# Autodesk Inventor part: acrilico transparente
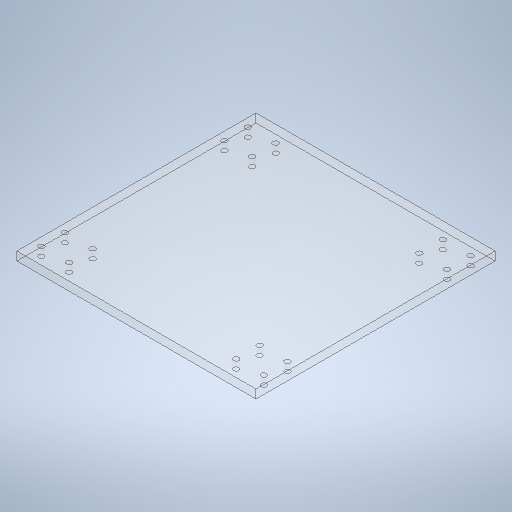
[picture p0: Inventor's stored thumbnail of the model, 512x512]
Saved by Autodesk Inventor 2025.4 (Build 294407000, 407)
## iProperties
Created: 2026-04
Part Number: acrilico transparente
Material: PET Plastic
Document SubType Name: Modeling
Designer: I11112
Density: 1.541 g/cm^3
Appearance: Polycarbonate - Clear
Author: I11112
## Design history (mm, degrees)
sketch "Sketch1"
  geometry: L1 (0, 0)-(220, 0); L2 (220, 0)-(220, -220); L3 (220, -220)-(0, -220); L4 (0, -220)-(0, 0)
  constraints: 8 end point, 2 parallel, 1 horizontal, 1 perpendicular
  dimensions: "d0" = 220 distance of L2.end L3.end; "d1" = 220 distance of L1.end L2.end
extrude "Extrusion1" new body sketch "Sketch1" distance "d2" = 8; taper "d3" = 0 deg
sketch "Sketch2"
  geometry: L1 (-220, 220)-(-220, 0) reference; L2 (0, 220)-(-220, 220) reference; L3 (0, 0)-(0, 220) reference; L4 (-212.5, 205)-(-186.9, 205); L5 (-212.5, 205)-(-199.7, 205); L6 (-200.3, 225.221)-(-200.3, 193.976); L7 (-33.1, 205)-(-7.5, 205); L8 (-7.5, 205)-(-20.3, 205); L9 (-20.3, 205)-(-20.3, 225.334); L10 (-212.5, 36.6)-(-199.7, 36.6); L11 (-200.3, 56.64)-(-200.3, 25.394); L12 (-212.5, 36.6)-(-186.9, 36.6); L13 (-20.3, 36.419)-(-20.3, 56.753); L14 (-33.1, 36.419)-(-7.5, 36.419); L15 (-7.5, 36.419)-(-20.3, 36.419); L16 (-220, 0)-(0, 0) reference; C1 r 2.5 at (-212.5, 205); C2 r 2.5 at (-186.9, 205); C3 r 2.5 at (-212.5, 183.4); C4 r 2.5 at (-186.9, 183.4); C5 r 2.5 at (-33.1, 205); C6 r 2.5 at (-7.5, 205); C7 r 2.5 at (-33.1, 183.4); C8 r 2.5 at (-7.5, 183.4); C9 r 2.5 at (-186.9, 36.6); C10 r 2.5 at (-212.5, 36.6); C11 r 2.5 at (-186.9, 15); C12 r 2.5 at (-212.5, 15); C13 r 2.5 at (-33.1, 36.419); C14 r 2.5 at (-33.1, 14.819); C15 r 2.5 at (-7.5, 14.819); C16 r 2.5 at (-7.5, 36.419); 4 further points
  constraints: 24 end point, 16 centre point, 8 midpoint, 8 vertical alignment, 4 horizontal, 4 vertical
  dimensions: "d4" = 5 diameter of C1; "d5" = 5 diameter of C2; "d6" = 5 diameter of C3; "d7" = 5 diameter of C4; "d8" = 25.6 distance of L4.end L4.start; "d9" = 21.6 distance of C3.centre L4.start; "d10" = 7.5 distance from line of L1 C3.centre; "d11" = 15 distance from line of L2 L4.start; "d12" = 21.6 distance of C4.centre L4.end (= d9); "d13" = 5 diameter of C5; "d14" = 5 diameter of C6; "d15" = 5 diameter of C7; "d16" = 5 diameter of C8; "d17" = 25.6 distance of L7.end L7.start; "d18" = 21.6 distance of C7.centre L7.start; "d19" = 21.6 distance of C8.centre L7.end (= d18); "d20" = 7.5 distance from line of L3 C8.centre; "d21" = 15 distance from line of L2 L7.end; "d22" = 180 distance from line of point (-20.3, 215.167) L6; "d23" = 13.4 horizontal distance of L4.end point (-200.3, 209.598) (derived); "d24" = 5 diameter of C10; "d25" = 5 diameter of C9; "d26" = 5 diameter of C12; "d27" = 5 diameter of C11; "d28" = 25.6 distance of L12.end L10.start; "d29" = 21.6 distance of C12.centre L10.start; "d30" = 21.6 distance of C11.centre L12.end (= d29); "d31" = 5 diameter of C13; "d32" = 5 diameter of C16; "d33" = 5 diameter of C14; "d34" = 5 diameter of C15; "d35" = 25.6 distance of L14.end L14.start; "d36" = 21.6 distance of C14.centre L14.start; "d37" = 21.6 distance of C15.centre L14.end (= d36); "d38" = 180 distance from line of point (-20.3, 46.586) L11; "d39" = 13.4 horizontal distance of L12.end point (-200.3, 41.017) (derived); "d40" = 7.5 distance from line of L1 C12.centre; "d41" = 15 distance from line of L16 C12.centre
extrude "Extrusion2" cut sketch "Sketch2" extent not by distance; stored distance "d42" = 0; taper "d43" = 0 deg
body "Solid1"
